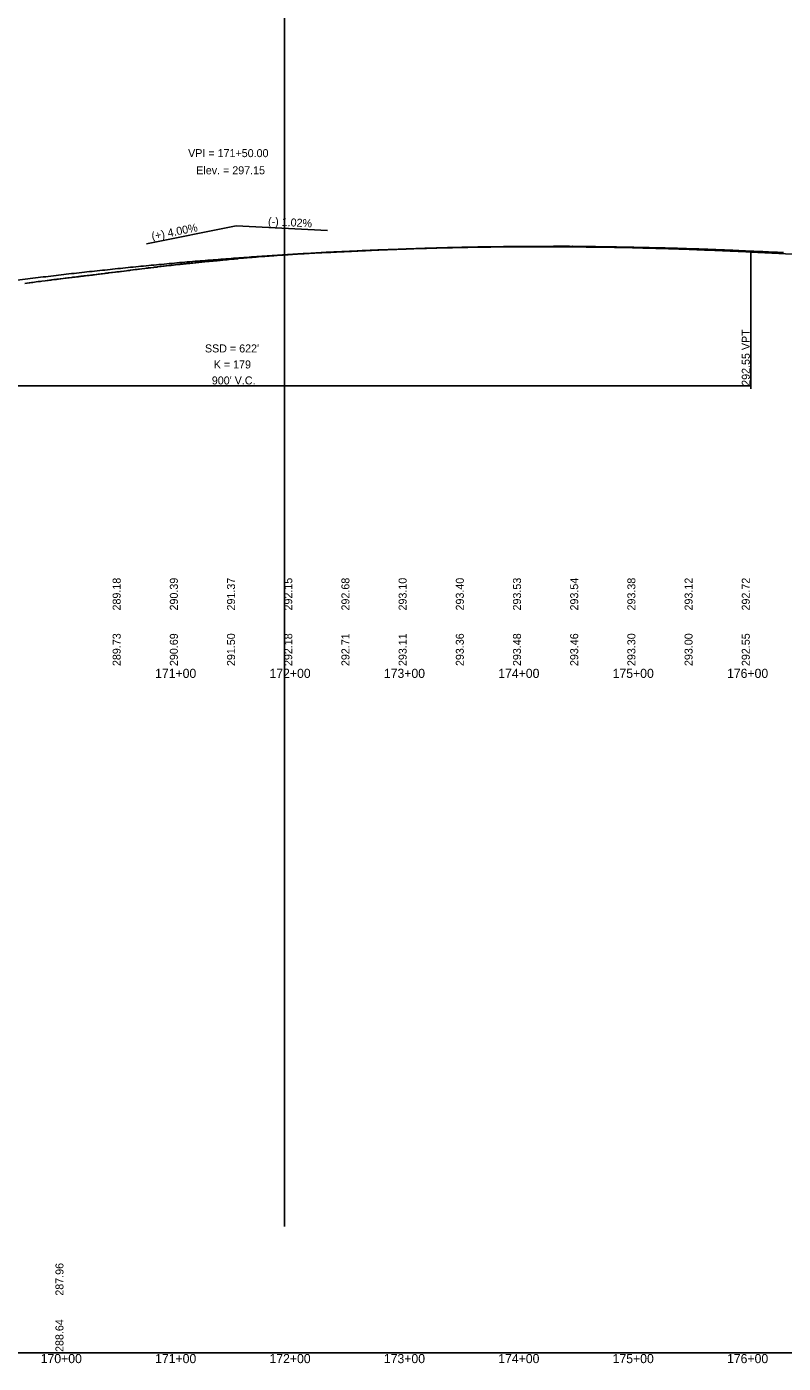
# Model space of a CAD drawing. Extents: x 1838386 to 1955906, y 719739 to 834437.
# Drawn here: x 1894330 to 1894991, y 825624 to 826793 of the extents above; entities that cross this region are included whole.
import ezdxf

# ---------------------------------------------------------------- set-up
doc = ezdxf.new("R2010")
doc.units = 0
for name, color, linetype in [('RD_DDB_GradeTX', 7, 'Continuous'), ('RD_DDB_Profile_EX', 7, 'Continuous'), ('RD_DDB_Profile_Lbl', 7, 'Continuous'), ('RD_DDB_Profile_PR', 7, 'Continuous'), ('RD_DDB_StaTX', 7, 'Continuous'), ('RD_DDB_StripGrade', 7, 'Continuous'), ('RD_DDB_VCLbl', 7, 'Continuous'), ('RD_GPK_Profile_Cell', 7, 'Continuous'), ('RD_Sketch1', 7, 'Continuous')]:
    doc.layers.add(name, color=color, linetype=linetype)

msp = doc.modelspace()

# ---------------------------------------------------------------- linework, layer by layer
at = {"layer": 'RD_DDB_GradeTX'}
for p in [(1894434.6, 826603.2), (1894593, 826614.8)]:
    msp.add_line(p, (1894513.1, 826618.9), dxfattribs=at)
at = {"layer": 'RD_DDB_Profile_EX'}
for points in [[(1894579.4, 826594.8), (1894580, 826594.8), (1894582, 826595), (1894584, 826595.1), (1894584.6, 826595.1), (1894585.5, 826595.1), (1894585.9, 826595.2), (1894587.3, 826595.2), (1894588, 826595.3), (1894589.8, 826595.4), (1894590.3, 826595.4), (1894591.9, 826595.5), (1894592.4, 826595.5), (1894593.9, 826595.6), (1894595, 826595.6), (1894595.9, 826595.6), (1894598, 826595.8), (1894598.7, 826595.8), (1894600.2, 826595.9), (1894600.9, 826595.9), (1894602.8, 826596), (1894603.8, 826596), (1894604.2, 826596.1), (1894605.4, 826596.1), (1894605.8, 826596.1), (1894607.2, 826596.2), (1894608, 826596.3), (1894608.3, 826596.3), (1894610.6, 826596.4), (1894612.2, 826596.5), (1894613.2, 826596.5), (1894613.8, 826596.5), (1894615.8, 826596.6), (1894616.8, 826596.7), (1894617.8, 826596.7), (1894618.4, 826596.8), (1894619.5, 826596.8), (1894621, 826596.9), (1894621.7, 826596.9), (1894623, 826597), (1894623.7, 826597), (1894624.2, 826597), (1894626.2, 826597.1), (1894627.7, 826597.2), (1894628.8, 826597.2), (1894629.3, 826597.2), (1894630.7, 826597.3), (1894631.3, 826597.3), (1894632.8, 826597.4), (1894634, 826597.4), (1894635.7, 826597.5), (1894636.5, 826597.6), (1894637.7, 826597.6), (1894639.1, 826597.7), (1894641.8, 826597.8), (1894644.3, 826597.9), (1894645.5, 826597.9), (1894646.9, 826598), (1894647.6, 826598), (1894648.1, 826598), (1894649.5, 826598.1), (1894650.2, 826598.1), (1894651.6, 826598.2), (1894652.1, 826598.2), (1894653.6, 826598.2), (1894654.7, 826598.3), (1894655.6, 826598.3), (1894657.2, 826598.4), (1894659, 826598.5), (1894659.8, 826598.5), (1894660.6, 826598.5), (1894661.6, 826598.6), (1894662.4, 826598.6), (1894663.6, 826598.6), (1894665, 826598.7), (1894666.9, 826598.8), (1894667.8, 826598.8), (1894670.2, 826598.9), (1894671.2, 826598.9), (1894672.8, 826599), (1894673.2, 826599), (1894673.6, 826599), (1894675.6, 826599.1), (1894676.6, 826599.1), (1894677.9, 826599.2), (1894678.5, 826599.2), (1894679.4, 826599.2), (1894680.5, 826599.3), (1894681.6, 826599.3), (1894683.1, 826599.3), (1894685.7, 826599.4), (1894688.3, 826599.5), (1894689.7, 826599.5), (1894690.8, 826599.6), (1894691.6, 826599.6), (1894692, 826599.6), (1894693.7, 826599.7), (1894694.5, 826599.7), (1894695.7, 826599.7), (1894696, 826599.7), (1894697.7, 826599.8)], [(1894697.7, 826599.8), (1894698.2, 826599.8), (1894698.6, 826599.8), (1894699.7, 826599.8), (1894701.2, 826599.9), (1894701.7, 826599.9), (1894703.8, 826599.9), (1894704.5, 826600), (1894705.7, 826600), (1894706.3, 826600), (1894707.7, 826600), (1894708.9, 826600), (1894709.7, 826600), (1894710.8, 826600.1), (1894711.7, 826600.1), (1894712.6, 826600.1), (1894713.8, 826600.1), (1894714.1, 826600.2), (1894714.6, 826600.2), (1894716.6, 826600.2), (1894717, 826600.2), (1894717.8, 826600.2), (1894719.2, 826600.2), (1894719.8, 826600.3), (1894721.8, 826600.3), (1894723.3, 826600.3), (1894724.4, 826600.4), (1894725.8, 826600.4), (1894726.9, 826600.4), (1894727.8, 826600.4), (1894729.6, 826600.4), (1894731, 826600.5), (1894732.1, 826600.5), (1894732.5, 826600.5), (1894734.7, 826600.5), (1894735.9, 826600.5), (1894737.2, 826600.6), (1894737.9, 826600.6), (1894739.9, 826600.6), (1894740.3, 826600.6), (1894742.1, 826600.6), (1894742.4, 826600.6), (1894744, 826600.6), (1894745, 826600.6), (1894746.8, 826600.7), (1894747.6, 826600.7), (1894748, 826600.7), (1894748.3, 826600.7), (1894749.7, 826600.7), (1894750.2, 826600.7), (1894752.7, 826600.7), (1894754, 826600.7), (1894754.6, 826600.7), (1894755.2, 826600.7), (1894757.4, 826600.7), (1894758.1, 826600.7), (1894759, 826600.7), (1894760.4, 826600.7), (1894760.9, 826600.7), (1894762.1, 826600.7), (1894763, 826600.7), (1894764.5, 826600.8), (1894765.6, 826600.8), (1894766.2, 826600.8), (1894767.1, 826600.8), (1894768.1, 826600.8), (1894768.5, 826600.8), (1894770.7, 826600.8), (1894772.2, 826600.8), (1894773.4, 826600.8), (1894774.3, 826600.8), (1894775.8, 826600.8), (1894776.3, 826600.8), (1894778, 826600.8), (1894778.4, 826600.8), (1894779.7, 826600.8), (1894780.4, 826600.8), (1894781, 826600.8), (1894782, 826600.8), (1894783.5, 826600.8), (1894784.4, 826600.8), (1894786.1, 826600.8), (1894787.7, 826600.8), (1894788.7, 826600.8), (1894790.5, 826600.9), (1894791.2, 826600.9), (1894792.2, 826600.9), (1894792.5, 826600.9), (1894793.8, 826600.9), (1894794.5, 826600.9), (1894796.6, 826600.9), (1894797.3, 826600.9), (1894798.5, 826600.9), (1894799, 826600.9), (1894800.6, 826600.9), (1894801.5, 826600.9), (1894802.7, 826600.9), (1894804.1, 826600.9), (1894804.7, 826600.8), (1894806.7, 826600.9), (1894807.1, 826600.9)], [(1894807.1, 826600.9), (1894808.8, 826600.8), (1894809.2, 826600.8), (1894811, 826600.8), (1894811.8, 826600.8), (1894812.8, 826600.8), (1894814.3, 826600.8), (1894817, 826600.8), (1894817.3, 826600.8), (1894819.4, 826600.8), (1894821, 826600.8), (1894822, 826600.7), (1894823, 826600.7), (1894823.5, 826600.7), (1894824.6, 826600.7), (1894825, 826600.7), (1894826.8, 826600.7), (1894827.2, 826600.7), (1894829.1, 826600.6), (1894829.8, 826600.6), (1894830.7, 826600.6), (1894832.3, 826600.6), (1894833.2, 826600.5), (1894834.8, 826600.5), (1894836.1, 826600.5), (1894836.9, 826600.5), (1894837.4, 826600.5), (1894839.3, 826600.4), (1894840, 826600.4), (1894841.4, 826600.4), (1894842.5, 826600.4), (1894843.4, 826600.4), (1894845.1, 826600.4), (1894845.5, 826600.4), (1894846.9, 826600.3), (1894847.9, 826600.3), (1894848.6, 826600.3), (1894850.2, 826600.3), (1894851.6, 826600.2), (1894852.7, 826600.2), (1894854.9, 826600.2), (1894855.3, 826600.2), (1894855.7, 826600.2), (1894857.1, 826600.1), (1894857.8, 826600.1), (1894859.8, 826600.1), (1894860.4, 826600.1), (1894861.1, 826600), (1894861.8, 826600), (1894863, 826600), (1894863.8, 826600), (1894865.6, 826600), (1894865.9, 826599.9), (1894867.4, 826599.9), (1894868.3, 826599.9), (1894870.7, 826599.9), (1894871.8, 826599.8), (1894873.2, 826599.8), (1894873.7, 826599.8), (1894874.1, 826599.8), (1894875.8, 826599.7), (1894876.2, 826599.7), (1894877.6, 826599.7), (1894878.3, 826599.7), (1894879.9, 826599.7), (1894880.2, 826599.7), (1894880.9, 826599.6), (1894882.3, 826599.6), (1894883.4, 826599.6), (1894885.3, 826599.5), (1894886.4, 826599.5), (1894888, 826599.5), (1894888.5, 826599.4), (1894890.5, 826599.4), (1894891.1, 826599.4), (1894892.6, 826599.3), (1894893.6, 826599.3), (1894894.6, 826599.3), (1894896.2, 826599.2), (1894896.7, 826599.2), (1894898.8, 826599.2), (1894900.7, 826599.1), (1894901.3, 826599.1), (1894902.8, 826599), (1894903.9, 826599), (1894905, 826599), (1894905.6, 826598.9), (1894906.4, 826598.9), (1894906.9, 826598.9), (1894909.1, 826598.8), (1894911.5, 826598.8), (1894913.1, 826598.7), (1894914.1, 826598.7), (1894915.6, 826598.6), (1894916.6, 826598.6), (1894917.5, 826598.6), (1894919.2, 826598.5), (1894919.8, 826598.5), (1894921.3, 826598.4), (1894921.7, 826598.4), (1894923.4, 826598.3)], [(1894923.4, 826598.3), (1894923.8, 826598.3), (1894924.3, 826598.3), (1894925.5, 826598.3), (1894926.8, 826598.2), (1894929, 826598.1), (1894929.6, 826598.1), (1894930, 826598.1), (1894930.6, 826598.1), (1894931.9, 826598), (1894932.3, 826598), (1894934.5, 826597.9), (1894935.8, 826597.8), (1894936.3, 826597.8), (1894937, 826597.8), (1894939, 826597.7), (1894939.5, 826597.7), (1894939.9, 826597.7), (1894941.5, 826597.6), (1894942.1, 826597.6), (1894942.6, 826597.6), (1894944.1, 826597.5), (1894944.6, 826597.5), (1894946.1, 826597.4), (1894947.2, 826597.4), (1894948.9, 826597.3), (1894949.8, 826597.3), (1894950.3, 826597.2), (1894952.4, 826597.2), (1894954.4, 826597.1), (1894955.1, 826597), (1894955.6, 826597), (1894957.4, 826597), (1894958.5, 826596.9), (1894960, 826596.8), (1894961.4, 826596.8), (1894962.1, 826596.7), (1894962.5, 826596.7), (1894963.6, 826596.7), (1894965, 826596.6), (1894965.5, 826596.6), (1894967.6, 826596.5), (1894968.8, 826596.5), (1894970.1, 826596.4), (1894971, 826596.3), (1894972.7, 826596.3), (1894973.1, 826596.3), (1894973.9, 826596.2), (1894975.2, 826596.2), (1894977.2, 826596.1), (1894977.8, 826596.1), (1894978.6, 826596), (1894980.3, 826595.9), (1894981.9, 826595.9), (1894982.8, 826595.8), (1894983.4, 826595.8), (1894985.5, 826595.7), (1894986.1, 826595.7), (1894986.4, 826595.7), (1894987.9, 826595.6), (1894989.7, 826595.5), (1894990.5, 826595.5), (1894991.7, 826595.4)], [(1894347.9, 826571), (1894348.6, 826571.1), (1894349.9, 826571.2), (1894351.2, 826571.4), (1894351.8, 826571.5), (1894353.8, 826571.8), (1894355.8, 826572), (1894356.5, 826572.1), (1894357.9, 826572.3), (1894359.1, 826572.4), (1894359.7, 826572.5), (1894361.8, 826572.8), (1894363.6, 826573), (1894364.4, 826573.1), (1894366, 826573.3), (1894367, 826573.4), (1894369.1, 826573.6), (1894369.7, 826573.7), (1894370, 826573.8), (1894372.3, 826574), (1894373.5, 826574.1), (1894375, 826574.3), (1894375.4, 826574.4), (1894376.7, 826574.6), (1894377.6, 826574.7), (1894379.4, 826574.9), (1894380.3, 826575), (1894381.4, 826575.1), (1894382.9, 826575.3), (1894383.3, 826575.3), (1894384.5, 826575.5), (1894385.6, 826575.6), (1894387.2, 826575.8), (1894388.2, 826575.9), (1894389.2, 826576), (1894390.8, 826576.3), (1894391.2, 826576.3), (1894392.3, 826576.5), (1894393.2, 826576.6), (1894393.5, 826576.6), (1894395.1, 826576.8), (1894396.1, 826576.9), (1894398.2, 826577.2), (1894399, 826577.3), (1894399.9, 826577.4), (1894401, 826577.5), (1894401.4, 826577.6), (1894402.2, 826577.7), (1894404.1, 826577.9), (1894405, 826578), (1894406.9, 826578.3), (1894407.5, 826578.3), (1894408.9, 826578.5), (1894409.3, 826578.6), (1894410.9, 826578.7), (1894412, 826578.9), (1894412.9, 826579), (1894414.8, 826579.3), (1894415.3, 826579.3), (1894417.3, 826579.6), (1894418.3, 826579.7), (1894419.9, 826579.9), (1894420.7, 826580), (1894422.7, 826580.3), (1894423.1, 826580.3), (1894424.7, 826580.5), (1894425.2, 826580.6), (1894426.6, 826580.7), (1894427.8, 826580.9), (1894428.6, 826581), (1894430.7, 826581.3), (1894433.1, 826581.6), (1894434.5, 826581.7), (1894435.8, 826581.9), (1894436.4, 826582), (1894438.4, 826582.2), (1894440.4, 826582.4), (1894441.1, 826582.5), (1894441.4, 826582.6), (1894442.4, 826582.7), (1894443.7, 826582.8), (1894444.3, 826582.9), (1894446.4, 826583.2), (1894447.6, 826583.3), (1894448.9, 826583.5), (1894450.2, 826583.6), (1894451.6, 826583.8), (1894452.1, 826583.8), (1894454.2, 826584.1), (1894456, 826584.2), (1894456.8, 826584.3), (1894458.3, 826584.5), (1894459.4, 826584.6), (1894460.1, 826584.7), (1894461.5, 826584.9), (1894462, 826584.9), (1894463.9, 826585.1), (1894464.6, 826585.2), (1894465.8, 826585.3), (1894466.4, 826585.4), (1894467.3, 826585.5)], [(1894467.3, 826585.5), (1894469.2, 826585.7), (1894469.9, 826585.8), (1894471.7, 826585.9), (1894472.7, 826586), (1894473.7, 826586.1), (1894475.1, 826586.3), (1894477, 826586.5), (1894477.7, 826586.6), (1894478.9, 826586.7), (1894479.5, 826586.7), (1894480.3, 826586.8), (1894481.5, 826586.9), (1894483, 826587.1), (1894484.8, 826587.3), (1894485.6, 826587.3), (1894487.4, 826587.5), (1894488.2, 826587.6), (1894489.4, 826587.7), (1894490.8, 826587.8), (1894491.5, 826587.9), (1894492.8, 826588), (1894493.4, 826588.1), (1894495.2, 826588.2), (1894496.1, 826588.3), (1894497.2, 826588.4), (1894497.7, 826588.5), (1894498.6, 826588.6), (1894499.2, 826588.6), (1894500.7, 826588.8), (1894501.3, 826588.8), (1894503.1, 826589), (1894504, 826589.1), (1894505.1, 826589.2), (1894506.5, 826589.4), (1894507, 826589.4), (1894508.6, 826589.6), (1894509.1, 826589.6), (1894510.3, 826589.7), (1894510.9, 826589.8), (1894511.7, 826589.9), (1894512.9, 826590), (1894514.3, 826590.1), (1894514.9, 826590.2), (1894516.9, 826590.4), (1894518.8, 826590.5), (1894519.5, 826590.6), (1894520.8, 826590.7), (1894522.2, 826590.8), (1894522.8, 826590.9), (1894524.8, 826591.1), (1894526.7, 826591.2), (1894527.4, 826591.3), (1894528.7, 826591.4), (1894529.1, 826591.4), (1894530, 826591.5), (1894530.6, 826591.5), (1894532.6, 826591.7), (1894534.6, 826591.9), (1894535.3, 826592), (1894536.6, 826592), (1894537.8, 826592.1), (1894538.5, 826592.2), (1894540.7, 826592.4), (1894541.6, 826592.4), (1894542.5, 826592.5), (1894543, 826592.5), (1894544.5, 826592.6), (1894545.6, 826592.7), (1894546.4, 826592.8), (1894547.9, 826592.9), (1894548.4, 826592.9), (1894548.9, 826593), (1894550.4, 826593.1), (1894550.8, 826593.1), (1894552.3, 826593.2), (1894553.4, 826593.3), (1894554.3, 826593.3), (1894556.3, 826593.5), (1894557.1, 826593.5), (1894558.3, 826593.6), (1894558.6, 826593.6), (1894560.4, 826593.7), (1894561.2, 826593.8), (1894562.2, 826593.8), (1894563.8, 826593.9), (1894564.2, 826594), (1894565.3, 826594), (1894566.7, 826594.1), (1894568.2, 826594.2), (1894569.1, 826594.2), (1894570.1, 826594.3), (1894571.6, 826594.4), (1894572.1, 826594.4), (1894572.9, 826594.5), (1894573.6, 826594.5), (1894574.2, 826594.5), (1894576.1, 826594.6), (1894576.8, 826594.7), (1894578.3, 826594.8), (1894579.4, 826594.8)], [(1894328.2, 826568.5), (1894330.2, 826568.8), (1894330.5, 826568.8), (1894332.1, 826569), (1894332.7, 826569.1), (1894334.1, 826569.2), (1894335.3, 826569.4), (1894338.2, 826569.8), (1894340, 826570), (1894340.6, 826570.1), (1894342, 826570.2), (1894343.2, 826570.4), (1894346, 826570.8), (1894347.9, 826571)]]:
    msp.add_lwpolyline(points, dxfattribs=at)
at = {"layer": 'RD_DDB_Profile_PR'}
msp.add_line((1894963.1, 826595.9), (1895238.1, 826581.8), dxfattribs=at)
msp.add_spline([(1894063.1, 826528.9), (1894081.1, 826532.4), (1894099.1, 826535.9), (1894117.1, 826539.3), (1894135.1, 826542.5), (1894153.1, 826545.7), (1894171.1, 826548.8), (1894189.1, 826551.8), (1894207.1, 826554.8), (1894225.1, 826557.6), (1894243.1, 826560.3), (1894261.1, 826563), (1894279.1, 826565.6), (1894297.1, 826568), (1894315.1, 826570.4), (1894333.1, 826572.7), (1894351.1, 826574.9), (1894369.1, 826577), (1894387.1, 826579), (1894405.1, 826580.9), (1894423.1, 826582.8), (1894441.1, 826584.5), (1894459.1, 826586.2), (1894477.1, 826587.8), (1894495.1, 826589.2), (1894513.1, 826590.6), (1894531.1, 826591.9), (1894549.1, 826593.1), (1894567.1, 826594.2), (1894585.1, 826595.3), (1894603.1, 826596.2), (1894621.1, 826597), (1894639.1, 826597.8), (1894657.1, 826598.4), (1894675.1, 826599), (1894693.1, 826599.5), (1894711.1, 826599.9), (1894729.1, 826600.2), (1894747.1, 826600.4), (1894765.1, 826600.5), (1894783.1, 826600.6), (1894801.1, 826600.5), (1894819.1, 826600.3), (1894837.1, 826600.1), (1894855.1, 826599.8), (1894873.1, 826599.3), (1894891.1, 826598.8), (1894909.1, 826598.2), (1894927.1, 826597.5), (1894945.1, 826596.8), (1894963.1, 826595.9)], degree=3, dxfattribs=at)
at = {"layer": 'RD_DDB_VCLbl'}
for p, q in [((1894963.1, 826476.4), (1894963.1, 826595.9)), ((1894063.1, 826478.9), (1894963.1, 826478.9))]:
    msp.add_line(p, q, dxfattribs=at)
at = {"layer": 'RD_GPK_Profile_Cell'}
msp.add_line((1878363.1, 825633.1), (1904963.1, 825633.1), dxfattribs=at)
at = {"layer": 'RD_Sketch1'}
msp.add_line((1894555.2, 825743.6), (1894555.2, 827268.6), dxfattribs=at)

# ---------------------------------------------------------------- texts
at = {"layer": 'RD_DDB_GradeTX'}
for s, rotation, p in [('(+) 4.00%', 11.3099, (1894439.8, 826606.2)), ('(-) 1.02%', 357.0768, (1894540.8, 826619.4))]:
    msp.add_text(s, height=7, rotation=rotation, dxfattribs=at).set_placement(p)
at = {"layer": 'RD_DDB_Profile_Lbl'}
for s, p in [('VPI = 171+50.00', (1894471.1, 826678.9)), ('Elev. = 297.15', (1894478.2, 826663.9))]:
    msp.add_text(s, height=7, dxfattribs=at).set_placement(p)
at = {"layer": 'RD_DDB_StaTX'}
for s, p in [('171+00', (1894442.2, 826223.4)), ('172+00', (1894542.2, 826223.4)), ('173+00', (1894642.2, 826223.4)), ('174+00', (1894742.2, 826223.4)), ('175+00', (1894842.2, 826223.4)), ('176+00', (1894942.2, 826223.4)), ('170+00', (1894342.2, 825624.1)), ('171+00', (1894442.2, 825624.1)), ('172+00', (1894542.2, 825624.1)), ('173+00', (1894642.2, 825624.1)), ('174+00', (1894742.2, 825624.1)), ('175+00', (1894842.2, 825624.1)), ('176+00', (1894942.2, 825624.1))]:
    msp.add_text(s, height=8, dxfattribs=at).set_placement(p)
at = {"layer": 'RD_DDB_StripGrade'}
for s, p in [('292.55 VPT', (1894962.1, 826478.9)), ('289.18', (1894412.1, 826282.4)), ('290.39', (1894462.1, 826282.4)), ('291.37', (1894512.1, 826282.4)), ('292.15', (1894562.1, 826282.4)), ('292.68', (1894612.1, 826282.4)), ('293.10', (1894662.1, 826282.4)), ('293.40', (1894712.1, 826282.4)), ('293.53', (1894762.1, 826282.4)), ('293.54', (1894812.1, 826282.4)), ('293.38', (1894862.1, 826282.4)), ('293.12', (1894912.1, 826282.4)), ('292.72', (1894962.1, 826282.4)), ('289.73', (1894412.1, 826233.8)), ('290.69', (1894462.1, 826233.8)), ('291.50', (1894512.1, 826233.8)), ('292.18', (1894562.1, 826233.8)), ('292.71', (1894612.1, 826233.8)), ('293.11', (1894662.1, 826233.8)), ('293.36', (1894712.1, 826233.8)), ('293.48', (1894762.1, 826233.8)), ('293.46', (1894812.1, 826233.8)), ('293.30', (1894862.1, 826233.8)), ('293.00', (1894912.1, 826233.8)), ('292.55', (1894962.1, 826233.8)), ('287.96', (1894362.1, 825683.1)), ('288.64', (1894362.1, 825633.9))]:
    msp.add_text(s, height=7, rotation=90, dxfattribs=at).set_placement(p)
at = {"layer": 'RD_DDB_VCLbl'}
for s, p in [("SSD = 622'", (1894485.8, 826508.1)), ('K = 179', (1894493.5, 826494.1)), ("900' V.C.", (1894491.8, 826480.1))]:
    msp.add_text(s, height=7, dxfattribs=at).set_placement(p)

doc.saveas('drawing.dxf')
